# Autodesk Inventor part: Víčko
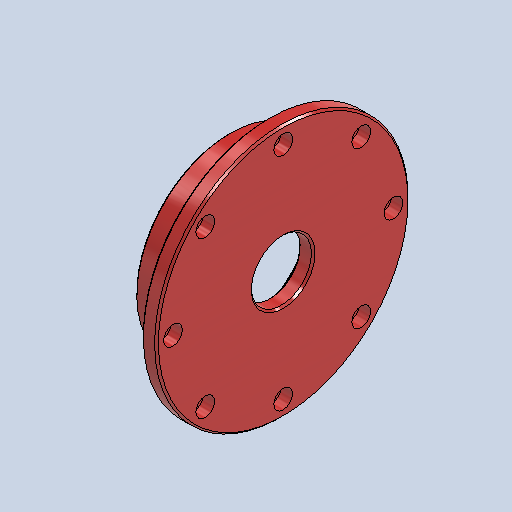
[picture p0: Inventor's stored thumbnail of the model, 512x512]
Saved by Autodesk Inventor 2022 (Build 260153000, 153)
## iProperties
Created: 2025-05
Part Number: Víčko
Material: Všeobecné
Document SubType Name: Modeling
Designer: jbart
Density: 1 g/cm^3
Appearance: Oranžovo-červená
Mass: 1078.22 g
Surface Area: 1745.39 cm^2
Volume: 1078.22 cm^3
Author: jbart
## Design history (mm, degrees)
sketch "Náčrt1"
  geometry: L1 (0, 0)-(52, 0); L2 (52, 32)-(52, 135); L3 (52, 135)-(36, 135); L4 (36, 135)-(36, 100); L5 (36, 100)-(-6, 100); L6 (-6, 100)-(-6, 90); L7 (-6, 90)-(36, 90); L8 (36, 90)-(36, 32); L9 (36, 32)-(52, 32); 3 further points
  constraints: 18 end point, 6 perpendicular, 3 midpoint, 2 horizontal, 2 vertical alignment, 1 vertical
  dimensions: "d0" = 52 distance of L1.start L1.end; "d5" = 16 distance of L2.end L3.end; "d6" = 270 diameter of L3 L1; "d7" = 180 diameter of L7 L1; "d8" = 64 diameter of L9 L1; "d9" = 42 distance of L6.end L7.end; "d10" = 200 diameter of L5 L1
revolve "Rotace1" sketch "Náčrt1" stored, may be unused: angle "d11" = 90 deg
chamfer "Zkosení1" distance "d12" = 2; stored, may be unused: second distance "d13" = 2, angle "d14" = 45 deg
fillet "Zaoblení1" dims "d15" = 5
sketch "Náčrt2" dims "d16" = 235
  geometry: L1 (0, 0)-(0, 117.5); C1 r 32 at (0, 0) reference; 3 further points
  constraints: 2 coincident, 2 end point, 1 vertical, 1 vertical alignment, 2 other
hole "Díra1" sketch "Náčrt2" at (0, 117.5) diameter "d17" = 13; stored, may be unused: countersink angle "d21" = 90 deg, drill point angle "d23" = 118 deg; dims "d18" = 15, "d19" = 20, "d20" = 12, "d22" = 20
pattern_circular "Kruhové pole1" dims angle "d25" = 360 deg
fillet "Zaoblení2" dims "d27" = 2
chamfer "Zkosení2" distance "d28" = 2; stored, may be unused: second distance "d29" = 2, angle "d30" = 45 deg
node "Těleso1"
